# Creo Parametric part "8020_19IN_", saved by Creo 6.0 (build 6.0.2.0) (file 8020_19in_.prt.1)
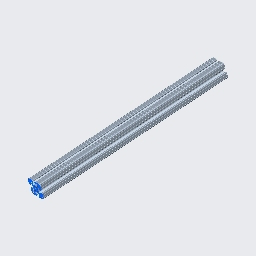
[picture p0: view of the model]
Units: Inch lbm Second (Pro/E Default); INCH, POUND, SECS

Created from: INLBS_PART_SOLID.PRT

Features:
  1. datum plane "RIGHT"
  2. datum plane "TOP"
  3. datum plane "FRONT"
  4. coordinate system
  5. curve "Project 1"
  6. sketch "Sketch 2"
  7. extrusion "Extrude 1"

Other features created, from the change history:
  sketch "Sketch 1"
